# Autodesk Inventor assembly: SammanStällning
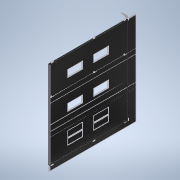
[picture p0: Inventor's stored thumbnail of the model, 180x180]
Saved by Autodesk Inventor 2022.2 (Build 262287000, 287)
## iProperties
Created: 2022-02
Part Number: SammanStällning
Document SubType Name: Assembly
Designer: cl
Author: cl
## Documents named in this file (18)
- G:\AutoCad\Carl Lund\3D-modeller systemlösningar\3D-modell-systemlösning-2022\SammanStällning.iam
- G:\AutoCad\Carl Lund\3D-modeller systemlösningar\3D-modell-systemlösning-2022\Parts\BladKomplett2022.iam
- G:\AutoCad\Carl Lund\3D-modeller systemlösningar\3D-modell-systemlösning-2022\Parts\MellanGångjärnH.ipt
- G:\AutoCad\Carl Lund\3D-modeller systemlösningar\3D-modell-systemlösning-2022\Parts\MellanGångjärnV.ipt
- G:\AutoCad\Carl Lund\3D-modeller systemlösningar\3D-modell-systemlösning-2022\Parts\Karmstyrning.ipt
- G:\AutoCad\Carl Lund\3D-modeller systemlösningar\3D-modell-systemlösning-2022\Parts\KarmgångjärnH.ipt
- G:\AutoCad\Carl Lund\3D-modeller systemlösningar\3D-modell-systemlösning-2022\Parts\KarmgångjärnV.ipt
- G:\AutoCad\Carl Lund\3D-modeller systemlösningar\3D-modell-systemlösning-2022\Parts\SidotätningUppe.ipt
- G:\AutoCad\Carl Lund\3D-modeller systemlösningar\3D-modell-systemlösning-2022\Parts\SidoTätning.ipt
- G:\AutoCad\Carl Lund\3D-modeller systemlösningar\3D-modell-systemlösning-2022\Parts\SläpList.ipt
- G:\AutoCad\Carl Lund\3D-modeller systemlösningar\3D-modell-systemlösning-2022\Parts\GummilistMellan.ipt
- G:\AutoCad\Carl Lund\3D-modeller systemlösningar\3D-modell-systemlösning-2022\Styrande.iam
- G:\AutoCad\Carl Lund\3D-modeller systemlösningar\3D-modell-systemlösning-2022\Parts\GarageregelHöger.ipt
- G:\AutoCad\Carl Lund\3D-modeller systemlösningar\3D-modell-systemlösning-2022\Parts\GarageregelVänster.ipt
- G:\AutoCad\Carl Lund\3D-modeller systemlösningar\3D-modell-systemlösning-2022\Parts\UppställningsbeslagHöger.ipt
- G:\AutoCad\Carl Lund\3D-modeller systemlösningar\3D-modell-systemlösning-2022\Parts\UppställningsbeslagVänster.ipt
- G:\AutoCad\Carl Lund\3D-modeller systemlösningar\3D-modell-systemlösning-2022\Parts\styrrulle.ipt
- G:\AutoCad\Carl Lund\3D-modeller systemlösningar\3D-modell-systemlösning-2022\Parts\Styrskena.ipt
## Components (43 placed, 16 different names)
1. BladKomplett2022:1 [sub-assembly] — Mate:1, Mate:2, Flush:1, Flush:2, Flush:3, Flush:8, Flush:28, Flush:29, Mate:28, Flush:30, Mate:42, Flush:73, Mate:39, Mate:43, Mate:47, Mate:48, Flush:99, Flush:100, Flush:101, Flush:102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
2. BladKomplett2022:2 [sub-assembly] — Flush:2, Flush:3, Flush:8, Flush:106, Mate:52, Flush:107, Flush:118, Flush:121, Mate:65, Flush:148, Flush:149, Mate:82, Flush:170, Flush:171
3. BladKomplett2022:3 [sub-assembly] — Flush:30, Flush:101, Flush:102, Mate:53, Flush:114, Flush:115
4. BladKomplett2022:4 [sub-assembly] — Flush:32, Flush:100, Flush:103, Mate:54, Flush:122, Flush:123, Flush:128, Mate:64, Flush:146, Flush:147
5. BladKomplett2022:5 [sub-assembly] — Flush:31, Flush:99, Flush:104, Flush:129, Mate:55, Flush:130, Mate:63, Flush:144, Flush:145, Mate:81, Flush:168, Flush:169
6. BladKomplett2022:6 [sub-assembly] — Mate:28, Flush:28, Flush:29, Flush:31, Flush:32, Mate:38, Flush:74, Mate:49, Mate:50, Flush:131, Flush:134, Flush:137, Mate:56, Flush:138, Flush:139, Mate:58, Mate:59, Mate:62, Flush:142, Flush:143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
7. GarageregelHöger:1 — Flush:156, Flush:157, Flush:158
8. GarageregelHöger:2 — Mate:77, Flush:154, Flush:155, Flush:156, Flush:157, Flush:158
9. GarageregelVänster:1 — Flush:161, Flush:162, Flush:163
10. GarageregelVänster:2 — Mate:78, Flush:159, Flush:160, Flush:161, Flush:162, Flush:163
11. Karmstyrning:2 — Mate:38, Mate:56, Flush:138, Flush:141
12. Karmstyrning:3 — Mate:39, Mate:43, Flush:140
13. Karmstyrning:4 — Mate:42, Mate:60, Mate:61, Flush:141
14. KarmgångjärnH:1 — Flush:74, Mate:49, Mate:50, Flush:166, Flush:167, Mate:80
15. KarmgångjärnV:1 — Flush:73, Mate:47, Mate:48, Flush:164, Flush:165, Mate:79
16. Karmstyrning:1 — Flush:139, Mate:58, Mate:59, Flush:140
17. MellanGångjärnV:3 — Flush:110, Flush:111, Flush:113
18. MellanGångjärnV:2 — Flush:108, Flush:109, Flush:110, Flush:111, Flush:112
19. MellanGångjärnV:1 — Flush:106, Mate:52, Flush:107, Flush:108, Flush:109
20. MellanGångjärnH:2 — Flush:116, Flush:117, Flush:118, Flush:119, Flush:120
21. MellanGångjärnH:3 — Flush:119, Flush:120, Flush:121
22. MellanGångjärnH:1 — Mate:53, Flush:114, Flush:115, Flush:116, Flush:117
23. MellanGångjärnV:6 — Flush:124, Flush:125, Flush:126, Flush:127, Flush:128
24. MellanGångjärnV:5 — Flush:126, Flush:127, Flush:129
25. MellanGångjärnV:4 — Mate:54, Flush:122, Flush:123, Flush:124, Flush:125
26. MellanGångjärnH:5 — Flush:132, Flush:133, Flush:134
27. MellanGångjärnH:6 — Flush:135, Flush:136, Flush:137
28. MellanGångjärnH:4 — Mate:55, Flush:130, Flush:131, Flush:132, Flush:133, Flush:135, Flush:136
29. GummilistMellan:2 — Mate:63, Flush:144, Flush:145
30. GummilistMellan:3 — Mate:64, Flush:146, Flush:147
31. GummilistMellan:4 — Mate:65, Flush:148, Flush:149
32. GummilistMellan:5 — Mate:66, Flush:150, Flush:151
33. SidotätningUppe:1 — Mate:67, Mate:68, Flush:152, Mate:71, Mate:74
34. SidoTätning:1 — Mate:69, Mate:70, Mate:71, Mate:76
35. SidoTätning:2 — Mate:72, Mate:73, Mate:74
36. SläpList:1 — Mate:75, Flush:153, Mate:76
37. GummilistMellan:1 — Mate:62, Flush:142, Flush:143
38. UppställningsbeslagVänster:1 — Flush:166, Flush:167, Mate:80
39. styrrulle:1 — Mate:81, Flush:168, Flush:169
40. styrrulle:2 — Mate:82, Flush:170, Flush:171, Tangent:1
41. Styrskena:1 — Mate:83, Flush:172, Tangent:1, Flush:174, Mate:176, Flush:175
42. Styrskena:2 — Flush:174, Mate:176, Flush:175
43. UppställningsbeslagHöger:1 — Flush:164, Flush:165, Mate:79, Mate:83, Flush:172
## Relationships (130: Flush 86, Mate 43, Tangent 1)
- Mate:1: BladKomplett2022:1
- Mate:2: BladKomplett2022:1
- Flush:1: BladKomplett2022:1
- Flush:2: BladKomplett2022:1 ↔ BladKomplett2022:2
- Flush:3: BladKomplett2022:1 ↔ BladKomplett2022:2
- Flush:8: BladKomplett2022:1 ↔ BladKomplett2022:2
- Mate:28: BladKomplett2022:1 ↔ BladKomplett2022:6
- Flush:28: BladKomplett2022:1 ↔ BladKomplett2022:6
- Flush:29: BladKomplett2022:1 ↔ BladKomplett2022:6
- Flush:30: BladKomplett2022:1 ↔ BladKomplett2022:3
- Flush:31: BladKomplett2022:5 ↔ BladKomplett2022:6
- Flush:32: BladKomplett2022:4 ↔ BladKomplett2022:6
- Mate:38: BladKomplett2022:6 ↔ Karmstyrning:2
- Mate:39: BladKomplett2022:1 ↔ Karmstyrning:3
- Mate:42: BladKomplett2022:1 ↔ Karmstyrning:4
- Mate:43: BladKomplett2022:1 ↔ Karmstyrning:3
- Flush:73: BladKomplett2022:1 ↔ KarmgångjärnV:1
- Mate:47: BladKomplett2022:1 ↔ KarmgångjärnV:1
- Mate:48: BladKomplett2022:1 ↔ KarmgångjärnV:1
- Flush:74: BladKomplett2022:6 ↔ KarmgångjärnH:1
- Mate:49: BladKomplett2022:6 ↔ KarmgångjärnH:1
- Mate:50: BladKomplett2022:6 ↔ KarmgångjärnH:1
- Flush:99: BladKomplett2022:1 ↔ BladKomplett2022:5
- Flush:100: BladKomplett2022:1 ↔ BladKomplett2022:4
- Flush:101: BladKomplett2022:1 ↔ BladKomplett2022:3
- Flush:102: BladKomplett2022:1 ↔ BladKomplett2022:3
- Flush:103: BladKomplett2022:1 ↔ BladKomplett2022:4
- Flush:104: BladKomplett2022:1 ↔ BladKomplett2022:5
- Flush:106: BladKomplett2022:2 ↔ MellanGångjärnV:1
- Mate:52: BladKomplett2022:2 ↔ MellanGångjärnV:1
- Flush:107: BladKomplett2022:2 ↔ MellanGångjärnV:1
- Flush:108: MellanGångjärnV:2 ↔ MellanGångjärnV:1
- Flush:109: MellanGångjärnV:2 ↔ MellanGångjärnV:1
- Flush:110: MellanGångjärnV:3 ↔ MellanGångjärnV:2
- Flush:111: MellanGångjärnV:3 ↔ MellanGångjärnV:2
- Flush:112: BladKomplett2022:1 ↔ MellanGångjärnV:2
- Flush:113: BladKomplett2022:1 ↔ MellanGångjärnV:3
- Mate:53: BladKomplett2022:3 ↔ MellanGångjärnH:1
- Flush:114: BladKomplett2022:3 ↔ MellanGångjärnH:1
- Flush:115: BladKomplett2022:3 ↔ MellanGångjärnH:1
- Flush:116: MellanGångjärnH:2 ↔ MellanGångjärnH:1
- Flush:117: MellanGångjärnH:2 ↔ MellanGångjärnH:1
- Flush:118: BladKomplett2022:2 ↔ MellanGångjärnH:2
- Flush:119: MellanGångjärnH:2 ↔ MellanGångjärnH:3
- Flush:120: MellanGångjärnH:2 ↔ MellanGångjärnH:3
- Flush:121: BladKomplett2022:2 ↔ MellanGångjärnH:3
- Mate:54: BladKomplett2022:4 ↔ MellanGångjärnV:4
- Flush:122: BladKomplett2022:4 ↔ MellanGångjärnV:4
- Flush:123: BladKomplett2022:4 ↔ MellanGångjärnV:4
- Flush:124: MellanGångjärnV:6 ↔ MellanGångjärnV:4
- Flush:125: MellanGångjärnV:6 ↔ MellanGångjärnV:4
- Flush:126: MellanGångjärnV:6 ↔ MellanGångjärnV:5
- Flush:127: MellanGångjärnV:6 ↔ MellanGångjärnV:5
- Flush:128: BladKomplett2022:4 ↔ MellanGångjärnV:6
- Flush:129: BladKomplett2022:5 ↔ MellanGångjärnV:5
- Mate:55: BladKomplett2022:5 ↔ MellanGångjärnH:4
- Flush:130: BladKomplett2022:5 ↔ MellanGångjärnH:4
- Flush:131: BladKomplett2022:6 ↔ MellanGångjärnH:4
- Flush:132: MellanGångjärnH:5 ↔ MellanGångjärnH:4
- Flush:133: MellanGångjärnH:5 ↔ MellanGångjärnH:4
- Flush:134: BladKomplett2022:6 ↔ MellanGångjärnH:5
- Flush:135: MellanGångjärnH:6 ↔ MellanGångjärnH:4
- Flush:136: MellanGångjärnH:6 ↔ MellanGångjärnH:4
- Flush:137: BladKomplett2022:6 ↔ MellanGångjärnH:6
- Mate:56: BladKomplett2022:6 ↔ Karmstyrning:2
- Flush:138: BladKomplett2022:6 ↔ Karmstyrning:2
- Flush:139: BladKomplett2022:6 ↔ Karmstyrning:1
- Mate:58: BladKomplett2022:6 ↔ Karmstyrning:1
- Mate:59: BladKomplett2022:6 ↔ Karmstyrning:1
- Flush:140: Karmstyrning:3 ↔ Karmstyrning:1
- Mate:60: BladKomplett2022:1 ↔ Karmstyrning:4
- Mate:61: BladKomplett2022:1 ↔ Karmstyrning:4
- Flush:141: Karmstyrning:2 ↔ Karmstyrning:4
- Mate:62: BladKomplett2022:6 ↔ GummilistMellan:1
- Flush:142: BladKomplett2022:6 ↔ GummilistMellan:1
- Flush:143: BladKomplett2022:6 ↔ GummilistMellan:1
- Mate:63: BladKomplett2022:5 ↔ GummilistMellan:2
- Flush:144: BladKomplett2022:5 ↔ GummilistMellan:2
- Flush:145: BladKomplett2022:5 ↔ GummilistMellan:2
- Mate:64: BladKomplett2022:4 ↔ GummilistMellan:3
- Flush:146: BladKomplett2022:4 ↔ GummilistMellan:3
- Flush:147: BladKomplett2022:4 ↔ GummilistMellan:3
- Mate:65: BladKomplett2022:2 ↔ GummilistMellan:4
- Flush:148: BladKomplett2022:2 ↔ GummilistMellan:4
- Flush:149: BladKomplett2022:2 ↔ GummilistMellan:4
- Mate:66: BladKomplett2022:1 ↔ GummilistMellan:5
- Flush:150: BladKomplett2022:1 ↔ GummilistMellan:5
- Flush:151: BladKomplett2022:1 ↔ GummilistMellan:5
- Mate:67: BladKomplett2022:1 ↔ SidotätningUppe:1
- Mate:68: BladKomplett2022:1 ↔ SidotätningUppe:1
- Flush:152: BladKomplett2022:6 ↔ SidotätningUppe:1
- Mate:69: BladKomplett2022:6 ↔ SidoTätning:1
- Mate:70: BladKomplett2022:6 ↔ SidoTätning:1
- Mate:71: SidotätningUppe:1 ↔ SidoTätning:1
- Mate:72: BladKomplett2022:1 ↔ SidoTätning:2
- Mate:73: BladKomplett2022:1 ↔ SidoTätning:2
- Mate:74: SidotätningUppe:1 ↔ SidoTätning:2
- Mate:75: BladKomplett2022:1 ↔ SläpList:1
- Flush:153: BladKomplett2022:1 ↔ SläpList:1
- Mate:76: SidoTätning:1 ↔ SläpList:1
- Mate:77: BladKomplett2022:1 ↔ GarageregelHöger:2
- Flush:154: BladKomplett2022:1 ↔ GarageregelHöger:2
- Flush:155: BladKomplett2022:1 ↔ GarageregelHöger:2
- Flush:156: GarageregelHöger:1 ↔ GarageregelHöger:2
- Flush:157: GarageregelHöger:1 ↔ GarageregelHöger:2
- Flush:158: GarageregelHöger:1 ↔ GarageregelHöger:2
- Mate:78: BladKomplett2022:6 ↔ GarageregelVänster:2
- Flush:159: BladKomplett2022:6 ↔ GarageregelVänster:2
- Flush:160: BladKomplett2022:6 ↔ GarageregelVänster:2
- Flush:161: GarageregelVänster:1 ↔ GarageregelVänster:2
- Flush:162: GarageregelVänster:1 ↔ GarageregelVänster:2
- Flush:163: GarageregelVänster:1 ↔ GarageregelVänster:2
- Flush:164: KarmgångjärnV:1 ↔ UppställningsbeslagHöger:1
- Flush:165: KarmgångjärnV:1 ↔ UppställningsbeslagHöger:1
- Mate:79: KarmgångjärnV:1 ↔ UppställningsbeslagHöger:1
- Flush:166: KarmgångjärnH:1 ↔ UppställningsbeslagVänster:1
- Flush:167: KarmgångjärnH:1 ↔ UppställningsbeslagVänster:1
- Mate:80: KarmgångjärnH:1 ↔ UppställningsbeslagVänster:1
- Mate:81: BladKomplett2022:5 ↔ styrrulle:1
- Flush:168: BladKomplett2022:5 ↔ styrrulle:1
- Flush:169: BladKomplett2022:5 ↔ styrrulle:1
- Mate:82: BladKomplett2022:2 ↔ styrrulle:2
- Flush:170: BladKomplett2022:2 ↔ styrrulle:2
- Flush:171: BladKomplett2022:2 ↔ styrrulle:2
- Mate:83: Styrskena:1 ↔ UppställningsbeslagHöger:1
- Flush:172: Styrskena:1 ↔ UppställningsbeslagHöger:1
- Tangent:1: styrrulle:2 ↔ Styrskena:1
- Flush:174: Styrskena:1 ↔ Styrskena:2
- Mate:176: Styrskena:1 ↔ Styrskena:2
- Flush:175: Styrskena:1 ↔ Styrskena:2
## Named parameters: Blad2 = 1691.66667 mm, Blad3 = 0, Blad4 = 0, Blad5 = 0, MGJ12Djup = 0, MGJ12Bredd = 0, MGJ56Djup = 48 mm, MGJ23Djup = 48 mm, MGJ45Djup = 48 mm, GarageRegel5 = 0, GarageRegel6 = 0, BladBredd = 1666.66667 mm, Fönsterhöjd = 862 mm, Blad2_1 = 1691.66667 mm, Blad3_1 = 0, Blad4_1 = 0, Blad5_1 = 0, Blad6 = 2025 mm, MGJ12Djup_1 = 0, MGJ12Bredd_1 = 0, MGJ2Djup = 0, MGJ2Bredd = 5012.5 mm, MGJ56Djup_1 = 48 mm, MGJ23Djup_1 = 48 mm, MGJ45Djup_1 = 48 mm, GarageRegel5_1 = 0, GarageRegel6_1 = 0, StyrskenaV = 3433.33333 mm, Styrrulle2Djup = 48 mm
